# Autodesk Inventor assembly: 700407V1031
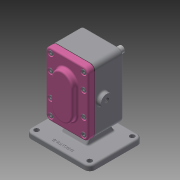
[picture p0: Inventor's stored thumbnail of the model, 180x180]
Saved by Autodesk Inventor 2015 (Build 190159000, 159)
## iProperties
Created: 2020-04
Part Number: 700407V1031
Document SubType Name: Assembly
Designer: now
Author: now
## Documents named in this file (11)
- C:\Users\now\Desktop\700407V1031\700407V1031.iam
- C:\Users\now\Desktop\700407V1031\700407V1031.ipt
- C:\Users\now\Desktop\700407V1031\Ű 6 x 6 x 18.ipt
- C:\Users\now\Desktop\700407V1031\개스킷.ipt
- C:\Users\now\Desktop\700407V1031\메인축.ipt
- C:\Users\now\Desktop\700407V1031\베어링부시.ipt
- C:\Users\now\Desktop\700407V1031\볼트 M5.ipt
- C:\Users\now\Desktop\700407V1031\서브축.ipt
- C:\Users\now\Desktop\700407V1031\스퍼기어.ipt
- C:\Users\now\Desktop\700407V1031\오일 실 16 28 7.ipt
- C:\Users\now\Desktop\700407V1031\커버.ipt
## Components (4 placed, 3 different names)
1. 700407V1031:1
2. Ű 6 x 6 x 18:1 — 각도:3, 각도:5
3. 개스킷:1
4. Ű 6 x 6 x 18:2 — 각도:1, 각도:4
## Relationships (4: Angle 4)
- 각도:1 [Angle]: Ű 6 x 6 x 18:2
- 각도:3 [Angle]: Ű 6 x 6 x 18:1
- 각도:4 [Angle]: Ű 6 x 6 x 18:2
- 각도:5 [Angle]: Ű 6 x 6 x 18:1
